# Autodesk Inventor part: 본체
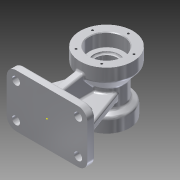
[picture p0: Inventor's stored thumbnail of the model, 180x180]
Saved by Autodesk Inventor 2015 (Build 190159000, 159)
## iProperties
Created: 2015-08
Part Number: 본체
Material: 알루미늄 6061
Document SubType Name: Modeling
Designer: PHO-02
Density: 2.7 g/cm^3
Appearance: 알루미늄 - 평지
Author: PHO-02
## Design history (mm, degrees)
sketch "스케치1"
  geometry: 1 further point
sketch "스케치2"
  geometry: L1 (47, 40)-(-47, 40); L2 (-61, 26)-(-61, -26); L3 (-47, -40)-(47, -40); L4 (61, -26)-(61, 26); L5 (61, 40)-(-61, -40); L6 (-61, 40)-(61, -40); A1 r 14 centre (47, -26) between (47, -40) and (61, -26); A2 r 14 centre (47, 26) between (61, 26) and (47, 40); A3 r 14 centre (-47, 26) between (-47, 40) and (-61, 26); A4 r 14 centre (-47, -26) between (-61, -26) and (-47, -40); 1 further point
  constraints: 12 end point, 8 point on circle, 8 point on line, 8 tangent, 4 centre point, 3 equal radius, 2 midpoint, 2 parallel, 1 horizontal, 1 perpendicular
  dimensions: "d0" = 122 distance of L6.end L5.end; "d1" = 80 distance of L5.end L6.start; "d2" = 14 radius of A1
extrude "돌출1" new body sketch "스케치2" distance "d3" = 12; taper "d4" = 0 deg
sketch "스케치3"
  geometry: L1 (125, -40)-(125, -20); L2 (125, -20)-(116, -14.804); L3 (130, 50)-(130, 30); L4 (130, 30)-(116, 13.315); L5 (116, -14.804)-(116, 13.315); L6 (116, 50)-(116, 30); L7 (110, -40)-(110, -23); L8 (110, -23)-(106, -23); L9 (106, -23)-(106, 27); L10 (116, 30)-(109, 30); L11 (109, 30)-(109, 30); L12 (106, 27)-(106, 27); L13 (90, -40)-(90, 88.543); L14 (116, 50)-(130, 50); L15 (110, -40)-(125, -40); A1 r 3 centre (106, 30) between (106, 27) and (109, 30); 1 further point
  constraints: 30 end point, 3 horizontal, 3 perpendicular, 2 point on circle, 2 tangent, 1 centre point, 1 vertical
  dimensions: "d7" = 35 distance of L13.start L1.start; "d17" = 20 distance of L6.start L6.end; "d22" = 17 distance of L7.start L7.end; "d24" = 7 distance of L6.end L10.end; "d26" = 3 radius of A1
revolve "회전1" sketch "스케치3" stored, may be unused: angle "d27" = 90 deg
sketch "스케치4"
  geometry: L1 (0, 0)-(20.554, 0); 4 further points
  constraints: 2 end point, 2 symmetric about line, 1 horizontal
hole "구멍1" sketch "스케치4" at (-47, 26), (-47, -26), (47, -26), (47, 26) diameter "d31" = 12; stored, may be unused: countersink angle "d35" = 90 deg, drill point angle "d37" = 118 deg; dims "d32" = 6, "d33" = 4, "d34" = 2, "d36" = 8
sketch "스케치5"
  geometry: L1 (12, -40)-(12, -30); L2 (12, -30)-(60.157, -30); L3 (60.157, -30)-(62.211, -22.558); L4 (62.211, -22.558)-(70.657, -16.395); L5 (70.657, -16.395)-(68.374, 22.638); L6 (68.374, 22.638)-(56.733, 33); L7 (12, 30)-(56.733, 37.888); L8 (12, 30)-(57.423, 30); L9 (56.733, 37.888)-(56.733, 33); L10 (12, -30)-(12, 30); L11 (12, 26)-(12, -26) reference; 2 further points
  constraints: 20 end point, 2 horizontal, 1 collinear, 1 equal length, 1 vertical
  dimensions: "d40" = 10 deg angle of L8 L7
extrude "돌출2" join sketch "스케치5" stored distance "d41" = 12; taper "d42" = 0 deg
sketch "스케치6"
  geometry: L1 (61, 12)-(51, 12); L2 (-51, 12)-(-25.091, 83.185); L3 (-6, 64.702)-(-6, 12); L4 (-6, 12)-(-51, 12); L5 (51, 12)-(25.091, 83.185); L6 (51, 12)-(126.753, 12); L7 (51, 12)-(6, 12); L8 (6, 64.702)-(6, 12); A1 r 26 centre (0, 90) between (6, 64.702) and (25.091, 83.185); A2 r 26 centre (0, 90) between (-25.091, 83.185) and (-6, 64.702); 3 further points
  constraints: 16 end point, 4 point on circle, 2 centre point, 2 horizontal, 1 coincident, 1 equal length, 1 vertical
  dimensions: "d44" = 10 distance of point (-61, 12) L2.start; "d46" = 110 deg angle of L6 L5
extrude "돌출3" join sketch "스케치6" stored distance "d47" = 12; taper "d48" = 0 deg
sketch "스케치7"
  geometry: L1 (-18, 30)-(-18, 36); L2 (-30, 30)-(-30, 36); L3 (18, 30)-(18, 36); L4 (30, 30)-(30, 36); A1 r 6 centre (-24, 30) between (-30, 30) and (-18, 30); A2 r 6 centre (-24, 36) between (-18, 36) and (-30, 36); A3 r 6 centre (24, 30) between (18, 30) and (30, 30); A4 r 6 centre (24, 36) between (30, 36) and (18, 36); 1 further point
  constraints: 10 point on circle, 8 end point, 4 centre point, 2 tangent
extrude "돌출4" cut sketch "스케치7" distance "d54" = 12; taper "d55" = 0 deg
sketch "스케치8"
  geometry: L1 (-40, 0)-(-40, 12) reference; 3 further points
  constraints: 1 other
feature "엠보싱1" sketch "스케치8" dims "d0" = 122, "d1" = 80, "d2" = 14, "d60" = 0.5, "d61" = 0
sketch "스케치9"
  geometry: C1 r 40 at (0, 0) reference; 6 further points
  constraints: 6 other
  dimensions: "d66" = 360 deg dimension on C1.centre point (0, 33) (derived)
hole "구멍2" sketch "스케치9" at (0, 33), (-31.385, 10.198), (-19.397, -26.698), (19.397, -26.698), (31.385, 10.198) diameter "d68" = 3.242; stored, may be unused: countersink angle "d72" = 90 deg, drill point angle "d74" = 118 deg; dims "d69" = 10, "d70" = 4, "d71" = 2, "d73" = 13
sketch "스케치10"
  geometry: C1 r 35 at (0, 0) reference; 6 further points
  constraints: 6 other
  dimensions: "d78" = 360 deg dimension on C1.centre point (0, 27) (derived)
hole "구멍3" sketch "스케치10" at (-25.679, 8.343), (0, 27), (25.679, 8.343), (15.87, -21.843), (-15.87, -21.843) diameter "d80" = 3.242; stored, may be unused: countersink angle "d84" = 90 deg, drill point angle "d86" = 118 deg; dims "d81" = 10, "d82" = 4, "d83" = 2, "d85" = 13
fillet "모깎기1" dims "d87" = 3
fillet "모깎기2" dims "d88" = 3, "d89" = 5, "d90" = 0.3
chamfer "모따기1" distance "d91" = 1; stored, may be unused: second distance "d92" = 2, angle "d93" = 45 deg
node "솔리드1"
